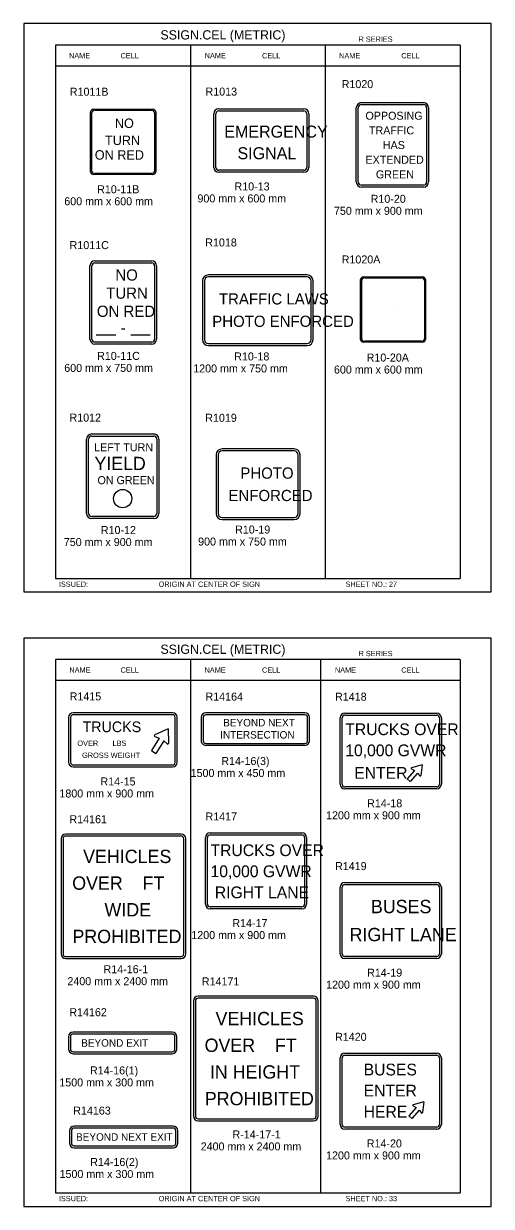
# Model space of a CAD drawing. Extents: x -12 to 6962, y -3756 to 679.
# Drawn here: x 400.1 to 575.4, y -926.5 to -483 of the extents above; entities that cross this region are included whole.
import ezdxf

# ---------------------------------------------------------------- set-up
doc = ezdxf.new("R2010")
doc.units = 0
for name, color, linetype in [('Level 1', 7, 'Continuous'), ('Level 2', 7, 'Continuous'), ('Level 3', 7, 'Continuous'), ('Level 63', 7, 'Continuous')]:
    doc.layers.add(name, color=color, linetype=linetype)

msp = doc.modelspace()

# ---------------------------------------------------------------- linework, layer by layer
at = {"layer": 'Level 1'}
for p, q in [((563.74, -491.06), (411.99, -491.06)), ((411.99, -491.06), (411.99, -691.06)), ((462.57, -491.06), (462.57, -691.06)), ((513.15, -491.06), (513.15, -691.06)), ((563.74, -491.06), (563.74, -691.06)), ((563.74, -498.98), (411.99, -498.98)), ((526.7, -513.37), (549.93, -513.37)), ((425.65, -538.29), (425.65, -516.38)), ((426.78, -515.48), (448, -515.48)), ((449.13, -516.38), (449.13, -538.29)), ((472.15, -536.89), (472.15, -516.79)), ((473.23, -515.71), (505.14, -515.71)), ((506.22, -516.79), (506.22, -536.89)), ((525.5, -542.37), (525.5, -514.57)), ((551.13, -514.57), (551.13, -542.37)), ((437.39, -527.34), (437.39, -527.34)), ((489.18, -526.84), (489.18, -526.84)), ((538.32, -528.47), (538.32, -528.47)), ((448, -539.2), (426.78, -539.2)), ((505.14, -537.97), (473.23, -537.97)), ((549.93, -543.57), (526.7, -543.57)), ((425.71, -601.31), (425.71, -573.81)), ((426.81, -572.71), (448.08, -572.71)), ((449.18, -573.81), (449.18, -601.31)), ((467.83, -579.48), (467.83, -601.48)), ((506.33, -577.98), (469.33, -577.98)), ((507.83, -601.48), (507.83, -579.48)), ((526.79, -601.17), (526.79, -579.26)), ((527.92, -578.36), (549.14, -578.36)), ((550.27, -579.26), (550.27, -601.17)), ((487.84, -590.44), (487.84, -590.44)), ((538.53, -590.22), (538.53, -590.22)), ((448.08, -602.41), (426.81, -602.41)), ((469.33, -602.98), (506.33, -602.98)), ((549.14, -602.07), (527.92, -602.07)), ((425.61, -637.62), (448.84, -637.62)), ((424.41, -666.62), (424.41, -638.82)), ((450.04, -638.82), (450.04, -666.62)), ((472.96, -644.71), (472.96, -666.71)), ((501.46, -643.21), (474.46, -643.21)), ((502.96, -666.71), (502.96, -644.71)), ((437.22, -652.72), (437.22, -652.72)), ((487.97, -655.73), (487.97, -655.73)), ((448.84, -667.82), (425.61, -667.82)), ((474.46, -668.21), (501.46, -668.21)), ((411.99, -691.06), (563.74, -691.06)), ((563.74, -721.41), (411.99, -721.41)), ((411.99, -721.41), (411.99, -921.41)), ((462.57, -721.41), (462.57, -921.41)), ((511.35, -721.41), (511.35, -921.41)), ((563.74, -721.41), (563.74, -921.41)), ((563.74, -729.33), (411.99, -729.33)), ((417.69, -743.11), (417.69, -759.97)), ((455.9, -742.11), (418.69, -742.11)), ((456.9, -759.97), (456.9, -743.11)), ((467.39, -743.16), (467.39, -751.86)), ((505.53, -742.16), (468.39, -742.16)), ((506.53, -751.86), (506.53, -743.16)), ((519.46, -768.22), (519.46, -743.27)), ((520.46, -742.27), (554.89, -742.27)), ((555.89, -743.27), (555.89, -768.22)), ((454.21, -747.47), (449.24, -749.7)), ((454.21, -747.47), (454.39, -752.81)), ((486.96, -745.48), (486.96, -745.48)), ((437.29, -751.54), (437.29, -751.54)), ((450.89, -750.9), (447.98, -755.57)), ((449.25, -750.25), (450.89, -750.9)), ((452.59, -751.95), (449.68, -756.63)), ((452.59, -751.95), (453.9, -753.05)), ((468.39, -752.86), (505.53, -752.86)), ((447.98, -755.57), (449.68, -756.63)), ((537.67, -755.75), (537.67, -755.75)), ((418.69, -760.97), (455.9, -760.97)), ((545.44, -762.42), (546.58, -763.1)), ((549.45, -760.97), (545.5, -762.01)), ((549.45, -760.97), (548.93, -764.94)), ((546.58, -763.1), (543.85, -766.2)), ((543.85, -766.2), (544.98, -767.19)), ((547.71, -764.09), (544.98, -767.19)), ((547.71, -764.09), (548.54, -765.06)), ((554.89, -769.22), (520.46, -769.22)), ((414.86, -788.6), (414.86, -831.83)), ((459.1, -787.6), (415.86, -787.6)), ((460.1, -831.83), (460.1, -788.6)), ((468.96, -813.14), (468.96, -788.19)), ((469.96, -787.19), (504.39, -787.19)), ((505.39, -788.19), (505.39, -813.14)), ((487.17, -800.66), (487.17, -800.66)), ((519.46, -831.74), (519.46, -806.79)), ((520.46, -805.79), (554.89, -805.79)), ((555.89, -806.79), (555.89, -831.74)), ((437.48, -810.21), (437.48, -810.21)), ((504.39, -814.14), (469.96, -814.14)), ((537.67, -819.26), (537.67, -819.26)), ((415.86, -832.83), (459.1, -832.83)), ((554.89, -832.74), (520.46, -832.74)), ((464.47, -849.4), (464.47, -892.63)), ((508.71, -848.4), (465.47, -848.4)), ((509.71, -892.63), (509.71, -849.4)), ((417.64, -862.84), (417.64, -867.47)), ((455.78, -861.84), (418.64, -861.84)), ((456.78, -867.47), (456.78, -862.84)), ((418.64, -868.47), (455.78, -868.47)), ((437.21, -865.16), (437.21, -865.16)), ((487.09, -871.02), (487.09, -871.02)), ((519.46, -895.76), (519.46, -870.81)), ((520.46, -869.81), (554.89, -869.81)), ((555.89, -870.81), (555.89, -895.76)), ((537.67, -883.29), (537.67, -883.29)), ((547.18, -889.44), (544.45, -892.54)), ((548.31, -890.43), (545.58, -893.53)), ((546.04, -888.76), (547.18, -889.44)), ((550.05, -887.31), (546.1, -888.35)), ((548.31, -890.43), (549.14, -891.4)), ((550.05, -887.31), (549.54, -891.28)), ((465.47, -893.63), (508.71, -893.63)), ((544.45, -892.54), (545.58, -893.53)), ((418.01, -898.11), (418.01, -902.74)), ((456.14, -897.11), (419.01, -897.11)), ((457.14, -902.74), (457.14, -898.11)), ((554.89, -896.76), (520.46, -896.76)), ((419.01, -903.74), (456.14, -903.74)), ((437.57, -900.43), (437.57, -900.43)), ((411.99, -921.41), (563.74, -921.41))]:
    msp.add_line(p, q, dxfattribs=at)
msp.add_circle((437.22, -661.1), 3.43, dxfattribs=at)
for centre, radius, start, end in [((526.7, -514.57), 1.2, 90, 180), ((549.93, -514.57), 1.2, 0, 90), ((473.23, -516.79), 1.08, 90, 180), ((505.14, -516.79), 1.08, 0, 90), ((473.23, -536.89), 1.08, 180, 270), ((505.14, -536.89), 1.08, 270, 0), ((526.7, -542.37), 1.2, 180, 270), ((549.93, -542.37), 1.2, 270, 0), ((426.81, -573.81), 1.1, 90, 180), ((448.08, -573.81), 1.1, 0, 90), ((469.33, -579.48), 1.5, 90, 180), ((506.33, -579.48), 1.5, 0, 90), ((426.81, -601.31), 1.1, 180, 270), ((448.08, -601.31), 1.1, 270, 0), ((469.33, -601.48), 1.5, 180, 270), ((506.33, -601.48), 1.5, 270, 0), ((425.61, -638.82), 1.2, 90, 180), ((448.84, -638.82), 1.2, 0, 90), ((474.46, -644.71), 1.5, 90, 180), ((501.46, -644.71), 1.5, 0, 90), ((425.61, -666.62), 1.2, 180, 270), ((448.84, -666.62), 1.2, 270, 0), ((474.46, -666.71), 1.5, 180, 270), ((501.46, -666.71), 1.5, 270, 0), ((418.69, -743.11), 1, 90, 180), ((455.9, -743.11), 1, 0, 90), ((468.39, -743.16), 1, 90, 180), ((505.53, -743.16), 1, 0, 90), ((520.46, -743.27), 1, 90, 180), ((554.89, -743.27), 1, 0, 90), ((449.36, -749.97), 0.3, 114.124, 248.3476), ((454.09, -752.82), 0.3, 230.0779, 1.968), ((468.39, -751.86), 1, 180.001, 270), ((505.53, -751.86), 1, 270, 0), ((418.69, -759.97), 1, 180, 270), ((455.9, -759.97), 1, 270, 0), ((545.56, -762.23), 0.225, 104.7504, 238.9741), ((548.71, -764.91), 0.225, 220.7043, 352.5945), ((520.46, -768.22), 1, 180, 270), ((554.89, -768.22), 1, 270, 0), ((415.86, -788.6), 1, 90, 180), ((459.1, -788.6), 1, 0, 90), ((469.96, -788.19), 1, 90, 180), ((504.39, -788.19), 1, 0, 90), ((520.46, -806.79), 1, 90, 180), ((554.89, -806.79), 1, 0, 90), ((469.96, -813.14), 1, 180, 270), ((504.39, -813.14), 1, 270, 0), ((415.86, -831.83), 1, 180, 270), ((459.1, -831.83), 1, 270, 0), ((520.46, -831.74), 1, 180, 270), ((554.89, -831.74), 1, 270, 0), ((465.47, -849.4), 1, 90, 180), ((508.71, -849.4), 1, 0, 90), ((418.64, -862.84), 1, 90, 180), ((455.78, -862.84), 1, 0, 90), ((418.64, -867.47), 1, 180, 270), ((455.78, -867.47), 1, 270, 0), ((520.46, -870.81), 1, 90, 180), ((554.89, -870.81), 1, 0, 90), ((546.16, -888.57), 0.225, 104.7504, 238.9741), ((549.31, -891.25), 0.225, 220.7043, 352.5945), ((465.47, -892.63), 1, 180, 270), ((508.71, -892.63), 1, 270, 0), ((520.46, -895.76), 1, 180, 270), ((554.89, -895.76), 1, 270, 0), ((419.01, -898.11), 1, 90, 180), ((456.14, -898.11), 1, 0, 90), ((419.01, -902.74), 1, 180, 270), ((456.14, -902.74), 1, 270, 0)]:
    msp.add_arc(centre, radius, start, end, dxfattribs=at)
for centre, major_axis, start_param, end_param in [((426.78, -516.38), (-1.13, 0), 4.712389, 6.283185), ((448, -516.38), (-1.13, 0), 3.141593, 4.712389), ((426.78, -538.29), (1.13, 0), 3.141593, 4.712389), ((448, -538.29), (1.13, 0), 4.712389, 6.283185), ((527.92, -579.26), (-1.13, 0), 4.712389, 6.283185), ((549.14, -579.26), (-1.13, 0), 3.141593, 4.712389), ((527.92, -601.17), (1.13, 0), 3.141593, 4.712389), ((549.14, -601.17), (1.13, 0), 4.712389, 6.283185)]:
    msp.add_ellipse(centre, major_axis=major_axis, ratio=0.802018, start_param=start_param, end_param=end_param, dxfattribs=at)
at = {"layer": 'Level 3'}
for p, q in [((526.7, -512.62), (549.93, -512.62)), ((425.2, -538.58), (425.2, -516.09)), ((426.42, -515.12), (448.36, -515.12)), ((449.58, -516.09), (449.58, -538.58)), ((471.4, -536.89), (471.4, -516.79)), ((473.23, -514.96), (505.14, -514.96)), ((506.97, -516.79), (506.97, -536.89)), ((524.75, -542.37), (524.75, -514.57)), ((551.88, -514.57), (551.88, -542.37)), ((448.36, -539.56), (426.42, -539.56)), ((505.14, -538.72), (473.23, -538.72)), ((549.93, -544.32), (526.7, -544.32)), ((426.81, -571.96), (448.08, -571.96)), ((424.96, -601.31), (424.96, -573.81)), ((449.93, -573.81), (449.93, -601.31)), ((467.08, -579.48), (467.08, -601.48)), ((506.33, -577.23), (469.33, -577.23)), ((508.58, -601.48), (508.58, -579.48)), ((526.34, -601.46), (526.34, -578.97)), ((527.56, -577.99), (549.51, -577.99)), ((550.72, -578.97), (550.72, -601.46)), ((437.44, -587.56), (437.44, -587.56)), ((427.31, -599.75), (434.64, -599.75)), ((440.24, -599.75), (447.57, -599.75)), ((549.51, -602.44), (527.56, -602.44)), ((448.08, -603.16), (426.81, -603.16)), ((469.33, -603.73), (506.33, -603.73)), ((425.61, -636.87), (448.84, -636.87)), ((423.66, -666.62), (423.66, -638.82)), ((450.79, -638.82), (450.79, -666.62)), ((501.46, -642.46), (474.46, -642.46)), ((472.21, -644.71), (472.21, -666.71)), ((503.71, -666.71), (503.71, -644.71)), ((448.84, -668.57), (425.61, -668.57)), ((474.46, -668.96), (501.46, -668.96)), ((416.94, -743.11), (416.94, -759.97)), ((455.9, -741.36), (418.69, -741.36)), ((457.65, -759.97), (457.65, -743.11)), ((466.64, -743.16), (466.64, -751.86)), ((505.53, -741.41), (468.39, -741.41)), ((507.28, -751.86), (507.28, -743.16)), ((518.71, -768.22), (518.71, -743.27)), ((520.46, -741.52), (554.89, -741.52)), ((556.64, -743.27), (556.64, -768.22)), ((505.53, -753.61), (468.39, -753.61)), ((418.69, -761.72), (455.9, -761.72)), ((554.89, -769.97), (520.46, -769.97)), ((414.11, -788.6), (414.11, -831.83)), ((459.1, -786.85), (415.86, -786.85)), ((460.85, -831.83), (460.85, -788.6)), ((468.21, -813.14), (468.21, -788.19)), ((469.96, -786.44), (504.39, -786.44)), ((506.14, -788.19), (506.14, -813.14)), ((518.71, -831.74), (518.71, -806.79)), ((520.46, -805.04), (554.89, -805.04)), ((556.64, -806.79), (556.64, -831.74)), ((504.39, -814.89), (469.96, -814.89)), ((415.86, -833.58), (459.1, -833.58)), ((554.89, -833.49), (520.46, -833.49)), ((463.72, -849.4), (463.72, -892.63)), ((508.71, -847.65), (465.47, -847.65)), ((510.46, -892.63), (510.46, -849.4)), ((416.89, -862.84), (416.89, -867.47)), ((455.78, -861.09), (418.64, -861.09)), ((457.53, -867.47), (457.53, -862.84)), ((520.46, -869.06), (554.89, -869.06)), ((418.64, -869.22), (455.78, -869.22)), ((518.71, -895.76), (518.71, -870.81)), ((556.64, -870.81), (556.64, -895.76)), ((465.47, -894.38), (508.71, -894.38)), ((417.26, -898.11), (417.26, -902.74)), ((456.14, -896.36), (419.01, -896.36)), ((457.89, -902.74), (457.89, -898.11)), ((554.89, -897.51), (520.46, -897.51)), ((419.01, -904.49), (456.14, -904.49))]:
    msp.add_line(p, q, dxfattribs=at)
for centre, radius, start, end in [((526.7, -514.57), 1.95, 90, 180), ((549.93, -514.57), 1.95, 0, 90), ((473.23, -516.79), 1.83, 90, 180), ((505.14, -516.79), 1.83, 0, 90), ((473.23, -536.89), 1.83, 180, 270), ((505.14, -536.89), 1.83, 270, 0), ((526.7, -542.37), 1.95, 180, 270), ((549.93, -542.37), 1.95, 270, 0), ((426.81, -573.81), 1.85, 90, 180), ((448.08, -573.81), 1.85, 0, 90), ((469.33, -579.48), 2.25, 90, 180), ((506.33, -579.48), 2.25, 0, 90), ((426.81, -601.31), 1.85, 180, 270), ((448.08, -601.31), 1.85, 270, 0), ((469.33, -601.48), 2.25, 180, 270), ((506.33, -601.48), 2.25, 270, 0), ((425.61, -638.82), 1.95, 90, 180), ((448.84, -638.82), 1.95, 0, 90), ((474.46, -644.71), 2.25, 90, 180), ((501.46, -644.71), 2.25, 0, 90), ((425.61, -666.62), 1.95, 180, 270), ((448.84, -666.62), 1.95, 270, 0), ((474.46, -666.71), 2.25, 180, 270), ((501.46, -666.71), 2.25, 270, 0), ((418.69, -743.11), 1.75, 90, 180), ((455.9, -743.11), 1.75, 0, 90), ((468.39, -743.16), 1.75, 90, 180), ((505.53, -743.16), 1.75, 0, 90), ((520.46, -743.27), 1.75, 90, 180), ((554.89, -743.27), 1.75, 0, 90), ((468.39, -751.86), 1.75, 179.9992, 270), ((505.53, -751.86), 1.75, 270, 0), ((418.69, -759.97), 1.75, 180, 270), ((455.9, -759.97), 1.75, 270, 0), ((520.46, -768.22), 1.75, 180, 270), ((554.89, -768.22), 1.75, 270, 0), ((415.86, -788.6), 1.75, 90, 180), ((459.1, -788.6), 1.75, 0, 90), ((469.96, -788.19), 1.75, 90, 180), ((504.39, -788.19), 1.75, 0, 90), ((520.46, -806.79), 1.75, 90, 180), ((554.89, -806.79), 1.75, 0, 90), ((469.96, -813.14), 1.75, 180, 270), ((504.39, -813.14), 1.75, 270, 0), ((415.86, -831.83), 1.75, 180, 270), ((459.1, -831.83), 1.75, 270, 0), ((520.46, -831.74), 1.75, 180, 270), ((554.89, -831.74), 1.75, 270, 0), ((465.47, -849.4), 1.75, 90, 180), ((508.71, -849.4), 1.75, 0, 90), ((418.64, -862.84), 1.75, 90, 180), ((455.78, -862.84), 1.75, 0, 90), ((418.64, -867.47), 1.75, 180, 270), ((455.78, -867.47), 1.75, 270, 0), ((520.46, -870.81), 1.75, 90, 180), ((554.89, -870.81), 1.75, 0, 90), ((465.47, -892.63), 1.75, 180, 270), ((508.71, -892.63), 1.75, 270, 0), ((520.46, -895.76), 1.75, 180, 270), ((554.89, -895.76), 1.75, 270, 0), ((419.01, -898.11), 1.75, 90, 180), ((456.14, -898.11), 1.75, 0, 90), ((419.01, -902.74), 1.75, 180, 270), ((456.14, -902.74), 1.75, 270, 0)]:
    msp.add_arc(centre, radius, start, end, dxfattribs=at)
for centre, major_axis, start_param, end_param in [((426.42, -516.09), (-1.22, 0), 4.712389, 6.283185), ((448.36, -516.09), (-1.22, 0), 3.141593, 4.712389), ((426.42, -538.58), (1.22, 0), 3.141593, 4.712389), ((448.36, -538.58), (1.22, 0), 4.712389, 6.283185), ((527.56, -578.97), (-1.22, 0), 4.712389, 6.283185), ((549.51, -578.97), (-1.22, 0), 3.141593, 4.712389), ((527.56, -601.46), (1.22, 0), 3.141593, 4.712389), ((549.51, -601.46), (1.22, 0), 4.712389, 6.283185)]:
    msp.add_ellipse(centre, major_axis=major_axis, ratio=0.802018, start_param=start_param, end_param=end_param, dxfattribs=at)
at = {"layer": 'Level 63'}
for points in [[(400.11, -696.11), (575.37, -696.11), (575.37, -483.01), (400.11, -483.01)], [(400.11, -926.46), (575.37, -926.46), (575.37, -713.36), (400.11, -713.36)]]:
    msp.add_lwpolyline(points, close=True, dxfattribs=at)

# ---------------------------------------------------------------- texts
at = {"layer": 'Level 1'}
for s, height, p in [('NO', 3.544, (434.29, -522.12)), ('TURN', 3.544, (430.59, -528.52)), ('ON RED', 3.544, (426.77, -534)), ('TRAFFIC LAWS', 4.2, (473.28, -588.31)), ('PHOTO ENFORCED', 4.2, (470.78, -596.71)), ('LEFT TURN', 3, (426.54, -643.35)), ('YIELD', 4.978, (426.63, -650.4)), ('PHOTO', 4.2, (481.31, -653.63)), ('ON GREEN', 3, (427.78, -655.68)), ('ENFORCED', 4.2, (476.86, -662.03)), ('TRUCKS', 4, (422.17, -748.66)), ('BEYOND NEXT', 2.8, (474.87, -746.51)), ('INTERSECTION', 2.8, (473.76, -751.06)), ('TRUCKS OVER', 4.4, (520.63, -749.78)), ('OVER       LBS', 2, (420.22, -753.82)), ('10,000 GVWR', 4.4, (520.63, -757.68)), ('GROSS WEIGHT', 2, (421.98, -758.32)), ('ENTER', 4.4, (524.01, -766.16)), ('VEHICLES', 5, (422.39, -797.75)), ('TRUCKS OVER', 4.4, (470.13, -795.13)), ('10,000 GVWR', 4.4, (470.13, -803.03)), ('OVER    FT', 5, (418.3, -807.75)), ('RIGHT LANE', 4.4, (471.74, -810.93)), ('BUSES', 5, (530.24, -816.55)), ('WIDE', 5, (430.39, -817.75)), ('PROHIBITED', 5, (418.38, -827.75)), ('RIGHT LANE', 5, (522.24, -827.05)), ('VEHICLES', 5, (472, -858.56)), ('BEYOND EXIT   ', 2.8, (421.66, -866.59)), ('OVER    FT', 5, (467.91, -868.56)), ('IN HEIGHT', 5, (469.91, -878.56)), ('BUSES', 4.4, (527.52, -877.37)), ('ENTER', 4.4, (527.52, -885.27)), ('PROHIBITED', 5, (467.99, -888.56)), ('HERE', 4.4, (527.52, -893.17)), ('BEYOND NEXT EXIT', 2.8, (419.74, -901.86))]:
    msp.add_text(s, height=height, dxfattribs=at).set_placement(p)
at = {"layer": 'Level 2'}
for s, p in [('R1020', (519.29, -507.19)), ('R1011B', (417.4, -510.03)), ('R1013', (468.26, -509.98)), ('R10-11B', (427.64, -546.61)), ('R10-13', (479.12, -545.54)), ('600 mm x 600 mm', (415.34, -551.11)), ('900 mm x 600 mm', (465.24, -550.04)), ('R10-20', (530.14, -550.19)), ('750 mm x 900 mm', (516.39, -554.69)), ('R1011C', (417.33, -567.55)), ('R1018', (468.16, -566.55)), ('R1020A', (519.29, -572.92)), ('R10-11C', (427.62, -609.09)), ('R10-18', (479.02, -609.29)), ('R10-20A', (528.64, -609.71)), ('600 mm x 750 mm', (415.32, -613.59)), ('1200 mm x 750 mm', (463.65, -613.79)), ('600 mm x 600 mm', (516.39, -614.21)), ('R1012', (417.28, -632.22)), ('R1019', (468.16, -632.29)), ('R10-12', (429.03, -674.38)), ('R10-19', (479.35, -674.19)), ('750 mm x 900 mm', (415.15, -678.88)), ('900 mm x 750 mm', (465.49, -678.69)), ('R1415', (417.35, -736.75)), ('R14164', (468.25, -736.83)), ('R1418', (516.81, -736.86)), ('R14-16(3)', (474.17, -760.98)), ('1500 mm x 450 mm', (462.68, -765.48)), ('R14-15', (428.88, -768.65)), ('1800 mm x 900 mm', (413.5, -773.15)), ('R14-18', (528.82, -776.83)), ('R14161', (417.27, -782.81)), ('R1417', (468.25, -781.78)), ('1200 mm x 900 mm', (513.44, -781.33)), ('R1419', (516.81, -800.38)), ('R14-17', (478.32, -821.74)), ('1200 mm x 900 mm', (462.94, -826.24)), ('R14-16-1', (430.04, -839.04)), ('R14-19', (528.81, -840.34)), ('2400 mm x 2400 mm', (416.5, -843.54)), ('R14171', (466.88, -843.62)), ('1200 mm x 900 mm', (513.44, -844.84)), ('R14162', (417.22, -855.17)), ('R1420', (516.81, -864.4)), ('R14-16(1)', (424.96, -876.99)), ('1500 mm x 300 mm', (413.47, -881.49)), ('R14163', (418.68, -892.06)), ('R-14-17-1', (478.37, -901)), ('2400 mm x 2400 mm', (466.45, -905.5)), ('R14-20', (528.69, -904.37)), ('R14-16(2)', (425.05, -911.34)), ('1200 mm x 900 mm', (513.44, -908.87)), ('1500 mm x 300 mm', (413.55, -915.84))]:
    msp.add_text(s, height=3, dxfattribs=at).set_placement(p)
at = {"layer": 'Level 3'}
for s, height, p in [('SSIGN.CEL (METRIC)', 3.4642, (451.37, -488.95)), ('R SERIES', 1.979, (525.61, -489.82)), ('NAME', 1.98, (417.12, -496.02)), ('CELL', 1.98, (436.42, -496.02)), ('NAME', 1.98, (467.97, -496.02)), ('CELL', 1.98, (489.44, -496.02)), ('NAME', 1.98, (518.33, -496.02)), ('CELL', 1.98, (541.64, -496.02)), ('OPPOSING', 3, (528.21, -519.03)), ('EMERGENCY', 4.5, (475.27, -525.74)), ('TRAFFIC', 3, (529.51, -524.53)), ('HAS', 3, (534.72, -530.03)), ('SIGNAL', 4.5, (480.23, -533.84)), ('EXTENDED', 3, (528.21, -535.53)), ('GREEN', 3, (532.11, -541.03)), ('NO', 4.2, (434.47, -579.35)), ('TURN', 4.2, (431.04, -586.15)), ('ON RED', 4.2, (427.54, -592.95)), ('-', 4.2, (436.41, -599.15)), ('ISSUED:', 1.98, (413.33, -694.18)), ('ORIGIN AT CENTER OF SIGN', 1.9795, (450.71, -694.18)), ('SHEET NO.: 27', 1.9795, (520.75, -694.18)), ('SSIGN.CEL (METRIC)', 3.4642, (451.37, -719.3)), ('R SERIES', 1.979, (525.61, -720.17)), ('NAME', 1.98, (417.26, -726.37)), ('CELL', 1.98, (436.42, -726.37)), ('NAME', 1.98, (467.9, -726.37)), ('CELL', 1.98, (489.44, -726.37)), ('NAME', 1.98, (516.76, -726.37)), ('CELL', 1.98, (541.64, -726.37)), ('ISSUED:', 1.98, (413.33, -924.53)), ('ORIGIN AT CENTER OF SIGN', 1.9795, (450.71, -924.53)), ('SHEET NO.: 33', 1.9795, (520.75, -924.53))]:
    msp.add_text(s, height=height, dxfattribs=at).set_placement(p)

doc.saveas('drawing.dxf')
